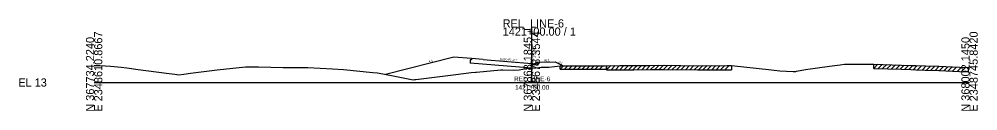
# Model space of a CAD drawing. Extents: x -26 to 403, y -10 to 6565.
# Drawn here: x -25.7 to 302.8, y 2490.3 to 2521.7 of the extents above; entities that cross this region are included whole.
import ezdxf

# ---------------------------------------------------------------- set-up
doc = ezdxf.new("R2010")
doc.units = 0
for name, color, linetype in [('RD_GPK_XS_Cell', 7, 'Continuous'), ('RD_XS_Base', 7, 'Continuous'), ('RD_XS_CurbBase', 7, 'Continuous'), ('RD_XS_CurbFront', 7, 'Continuous'), ('RD_XS_CurbTop', 7, 'Continuous'), ('RD_XS_EarthShd', 7, 'Continuous'), ('RD_XS_ExGround', 7, 'Continuous'), ('RD_XS_ExPaveRet', 7, 'Continuous'), ('RD_XS_Pave', 7, 'Continuous'), ('RD_XS_PaveShd', 7, 'Continuous'), ('RD_XS_TieSlope', 7, 'Continuous'), ('RD_XS_TX_Elev_EX', 7, 'Continuous'), ('RD_XS_TX_Elev_PR', 7, 'Continuous'), ('RD_XS_TX_Slope', 7, 'Continuous'), ('RD_XS_TX_Station', 7, 'Continuous'), ('RD_XS_TX_TOC', 7, 'Continuous')]:
    doc.layers.add(name, color=color, linetype=linetype)

msp = doc.modelspace()

# ---------------------------------------------------------------- linework, layer by layer
at = {"layer": 'RD_GPK_XS_Cell'}
for p, q in [((150, 2500), (150, 2518.83)), ((0, 2500), (150, 2500)), ((150, 2500), (300, 2500))]:
    msp.add_line(p, q, dxfattribs=at)
at = {"layer": 'RD_XS_Base'}
for p, q in [((129.32, 2507.74), (128.82, 2507.78)), ((128.82, 2507.78), (128.82, 2506.59)), ((129.32, 2508.19), (129.32, 2507.74)), ((150, 2504.89), (128.82, 2506.59))]:
    msp.add_line(p, q, dxfattribs=at)
at = {"layer": 'RD_XS_CurbBase'}
for p, q in [((152, 2506.93), (152, 2505.93)), ((151.5, 2505.93), (150, 2506.01)), ((150, 2504.89), (150, 2506.01)), ((152, 2505.93), (151.5, 2505.93))]:
    msp.add_line(p, q, dxfattribs=at)
at = {"layer": 'RD_XS_CurbFront'}
msp.add_line((150, 2506.01), (150, 2506.51), dxfattribs=at)
at = {"layer": 'RD_XS_CurbTop'}
for p, q in [((151.42, 2506.43), (151.5, 2506.93)), ((151.5, 2506.93), (152, 2506.93)), ((150, 2506.53), (150, 2506.51)), ((150, 2506.51), (151.42, 2506.43))]:
    msp.add_line(p, q, dxfattribs=at)
at = {"layer": 'RD_XS_EarthShd'}
for p, q in [((123.32, 2508.67), (99.82, 2502.79)), ((129.32, 2508.19), (123.32, 2508.67)), ((152, 2506.93), (158, 2507.05))]:
    msp.add_line(p, q, dxfattribs=at)
at = {"layer": 'RD_XS_ExGround'}
msp.add_lwpolyline([(0, 2505.86), (1.94, 2505.8), (5.57, 2505.59), (9.3, 2505.27), (11.18, 2504.99), (15.07, 2504.43), (24.81, 2503.2), (27.69, 2502.87), (28.97, 2502.63), (30.75, 2502.86), (33.03, 2503.22), (42.12, 2504.36), (51.88, 2505.42), (53.08, 2505.41), (53.81, 2505.41), (56.36, 2505.38), (64.8, 2505.15), (68.34, 2505.15), (73.19, 2505.1), (77.42, 2504.94), (81.73, 2504.66), (85.47, 2504.42), (95.56, 2503.46), (97.13, 2503.31), (102.43, 2502.29), (109.37, 2500.95), (109.83, 2500.99), (110.26, 2501.06), (123.99, 2502.76), (129.18, 2503.39), (130.69, 2503.56), (131.07, 2503.56), (139.35, 2504.35), (140.07, 2504.35), (143.6, 2504.27), (145.64, 2504.29), (146.88, 2504.53), (147.89, 2504.79), (149.17, 2504.87), (150, 2504.91), (151.48, 2504.98), (153.17, 2505.2), (155.85, 2505.27), (159.73, 2505.67), (161.45, 2505.71), (167.86, 2505.7), (174.93, 2505.75), (180.32, 2505.8), (184.98, 2505.79), (190.5, 2505.84), (195.39, 2505.92), (206.79, 2505.75), (216.89, 2505.82), (218.37, 2505.81), (232.11, 2504.3), (235.01, 2504), (239.59, 2503.77), (240.03, 2503.74), (240.42, 2503.79), (240.74, 2503.86), (243.8, 2504.45), (252.05, 2505.54), (255.65, 2506.1), (257.12, 2506.24), (267.21, 2506.28), (276.63, 2505.95), (279.83, 2505.85), (281.57, 2505.81), (284.83, 2505.66), (289.46, 2505.56), (296.54, 2505.2), (300, 2505.11)], dxfattribs=at)
at = {"layer": 'RD_XS_ExPaveRet'}
for p, q in [((159.73, 2504.52), (160.9, 2505.7)), ((159.73, 2504.52), (159.73, 2505.67)), ((159.73, 2504.52), (161.45, 2504.57)), ((161.23, 2504.56), (162.37, 2505.71)), ((161.45, 2504.57), (167.86, 2504.55)), ((162.73, 2504.56), (163.87, 2505.7)), ((164.23, 2504.56), (165.37, 2505.7)), ((165.73, 2504.56), (166.87, 2505.7)), ((167.23, 2504.55), (168.37, 2505.7)), ((167.86, 2504.55), (174.93, 2504.61)), ((168.73, 2504.56), (169.88, 2505.71)), ((170.23, 2504.57), (171.38, 2505.72)), ((171.73, 2504.58), (172.88, 2505.74)), ((173.23, 2504.6), (174.38, 2505.75)), ((174.93, 2504.61), (175.61, 2504.62)), ((175.61, 2505.76), (175.61, 2504.62)), ((175.64, 2504.32), (177.09, 2505.77)), ((175.64, 2504.32), (175.64, 2505.76)), ((175.64, 2504.32), (180.32, 2504.36)), ((177.14, 2504.34), (178.59, 2505.78)), ((178.64, 2504.35), (180.09, 2505.8)), ((180.14, 2504.36), (181.58, 2505.8)), ((180.32, 2504.36), (184.98, 2504.36)), ((181.64, 2504.36), (183.08, 2505.8)), ((183.14, 2504.36), (184.58, 2505.79)), ((184.64, 2504.36), (186.09, 2505.8)), ((184.98, 2504.36), (190.5, 2504.4)), ((186.14, 2504.37), (187.59, 2505.81)), ((187.64, 2504.38), (189.09, 2505.83)), ((189.14, 2504.39), (190.59, 2505.84)), ((190.5, 2504.4), (195.39, 2504.48)), ((190.64, 2504.4), (192.1, 2505.86)), ((192.14, 2504.43), (193.6, 2505.89)), ((193.64, 2504.45), (195.1, 2505.91)), ((195.14, 2504.48), (196.56, 2505.9)), ((195.39, 2504.48), (206.79, 2504.32)), ((196.64, 2504.46), (198.06, 2505.88)), ((198.14, 2504.44), (199.56, 2505.86)), ((199.64, 2504.42), (201.06, 2505.84)), ((201.14, 2504.4), (202.56, 2505.82)), ((202.64, 2504.38), (204.06, 2505.79)), ((204.14, 2504.36), (205.56, 2505.77)), ((205.64, 2504.33), (207.06, 2505.76)), ((206.79, 2504.32), (216.89, 2504.38)), ((207.14, 2504.32), (208.59, 2505.77)), ((208.64, 2504.33), (210.09, 2505.77)), ((210.14, 2504.34), (211.59, 2505.78)), ((211.64, 2504.35), (213.09, 2505.79)), ((213.14, 2504.36), (214.59, 2505.8)), ((214.64, 2504.37), (216.09, 2505.81)), ((216.14, 2504.38), (217.58, 2505.81)), ((216.89, 2504.38), (218.37, 2504.37)), ((218.37, 2505.81), (218.37, 2504.37)), ((267.21, 2504.84), (267.21, 2506.28)), ((267.21, 2504.84), (268.6, 2506.23)), ((267.21, 2504.84), (276.63, 2504.51)), ((268.71, 2504.79), (270.1, 2506.18)), ((270.21, 2504.74), (271.6, 2506.13)), ((271.71, 2504.68), (273.1, 2506.07)), ((273.21, 2504.63), (274.6, 2506.02)), ((274.71, 2504.58), (276.1, 2505.97)), ((276.21, 2504.53), (277.6, 2505.92)), ((276.63, 2504.51), (279.83, 2504.41)), ((277.71, 2504.48), (279.1, 2505.87)), ((279.21, 2504.43), (280.61, 2505.83)), ((279.83, 2504.41), (281.57, 2504.37)), ((280.71, 2504.39), (282.1, 2505.78)), ((281.57, 2504.37), (284.83, 2504.22)), ((282.21, 2504.34), (283.58, 2505.71)), ((283.71, 2504.27), (285.09, 2505.65)), ((284.83, 2504.22), (289.46, 2504.12)), ((285.21, 2504.21), (286.62, 2505.62)), ((286.71, 2504.18), (288.12, 2505.59)), ((288.21, 2504.15), (289.61, 2505.55)), ((289.46, 2504.12), (296.54, 2503.76)), ((289.71, 2504.11), (291.08, 2505.47)), ((291.21, 2504.03), (292.58, 2505.4)), ((292.71, 2503.95), (294.08, 2505.32)), ((294.21, 2503.88), (295.58, 2505.24)), ((295.71, 2503.8), (297.09, 2505.18)), ((296.54, 2503.76), (299.51, 2503.69)), ((297.21, 2503.74), (298.61, 2505.15)), ((299.51, 2505.13), (299.51, 2503.69))]:
    msp.add_line(p, q, dxfattribs=at)
at = {"layer": 'RD_XS_Pave'}
msp.add_line((133.32, 2507.87), (150, 2506.53), dxfattribs=at)
at = {"layer": 'RD_XS_PaveShd'}
msp.add_line((133.32, 2507.87), (129.32, 2508.19), dxfattribs=at)
at = {"layer": 'RD_XS_TieSlope'}
msp.add_line((158, 2507.05), (160.72, 2505.69), dxfattribs=at)

# ---------------------------------------------------------------- texts
at = {"layer": 'RD_GPK_XS_Cell'}
for s, p in [('REL_LINE-6', (140, 2518.83)), ('1421+00.00 / 1', (140, 2516.03)), ('EL 13', (-26, 2498.6))]:
    msp.add_text(s, height=2.8, dxfattribs=at).set_placement(p)
for s, p in [('E 2348610.8667', (2.8, 2490)), ('E 2348678.3544', (152.8, 2490)), ('E 2348745.8420', (302.8, 2490)), ('N 367734.2240', (0, 2490)), ('N 367868.1845', (150, 2490)), ('N 368002.1450', (300, 2490))]:
    msp.add_text(s, height=2.8, rotation=90, dxfattribs=at).set_placement(p)
at = {"layer": 'RD_XS_TX_Elev_EX'}
msp.add_text('17.91', height=1, rotation=90, dxfattribs=at).set_placement((150.5, 2504.91))
at = {"layer": 'RD_XS_TX_Elev_PR'}
msp.add_text(' 19.53', height=1.2, rotation=90, dxfattribs=at).set_placement((151.2, 2507.81))
at = {"layer": 'RD_XS_TX_Slope'}
for s, rotation, p in [('4:1', 14.0362, (114.75, 2506.78)), ('0.080 FT./FT.', 355.4279, (139, 2507.66)), ('50:1', 1.1458, (154.12, 2507.21)), ('2:1', 333.4349, (159.06, 2506.74))]:
    msp.add_text(s, height=0.75, rotation=rotation, dxfattribs=at).set_placement(p)
at = {"layer": 'RD_XS_TX_Station'}
for s, p in [('REL_LINE-6', (143.92, 2500.43)), ('1421+00.00', (144.23, 2497.53))]:
    msp.add_text(s, height=1.6, dxfattribs=at).set_placement(p)
at = {"layer": 'RD_XS_TX_TOC'}
msp.add_text('TOCRT', height=0.05, dxfattribs=at).set_placement((151.22, 2506.88))

doc.saveas('drawing.dxf')
